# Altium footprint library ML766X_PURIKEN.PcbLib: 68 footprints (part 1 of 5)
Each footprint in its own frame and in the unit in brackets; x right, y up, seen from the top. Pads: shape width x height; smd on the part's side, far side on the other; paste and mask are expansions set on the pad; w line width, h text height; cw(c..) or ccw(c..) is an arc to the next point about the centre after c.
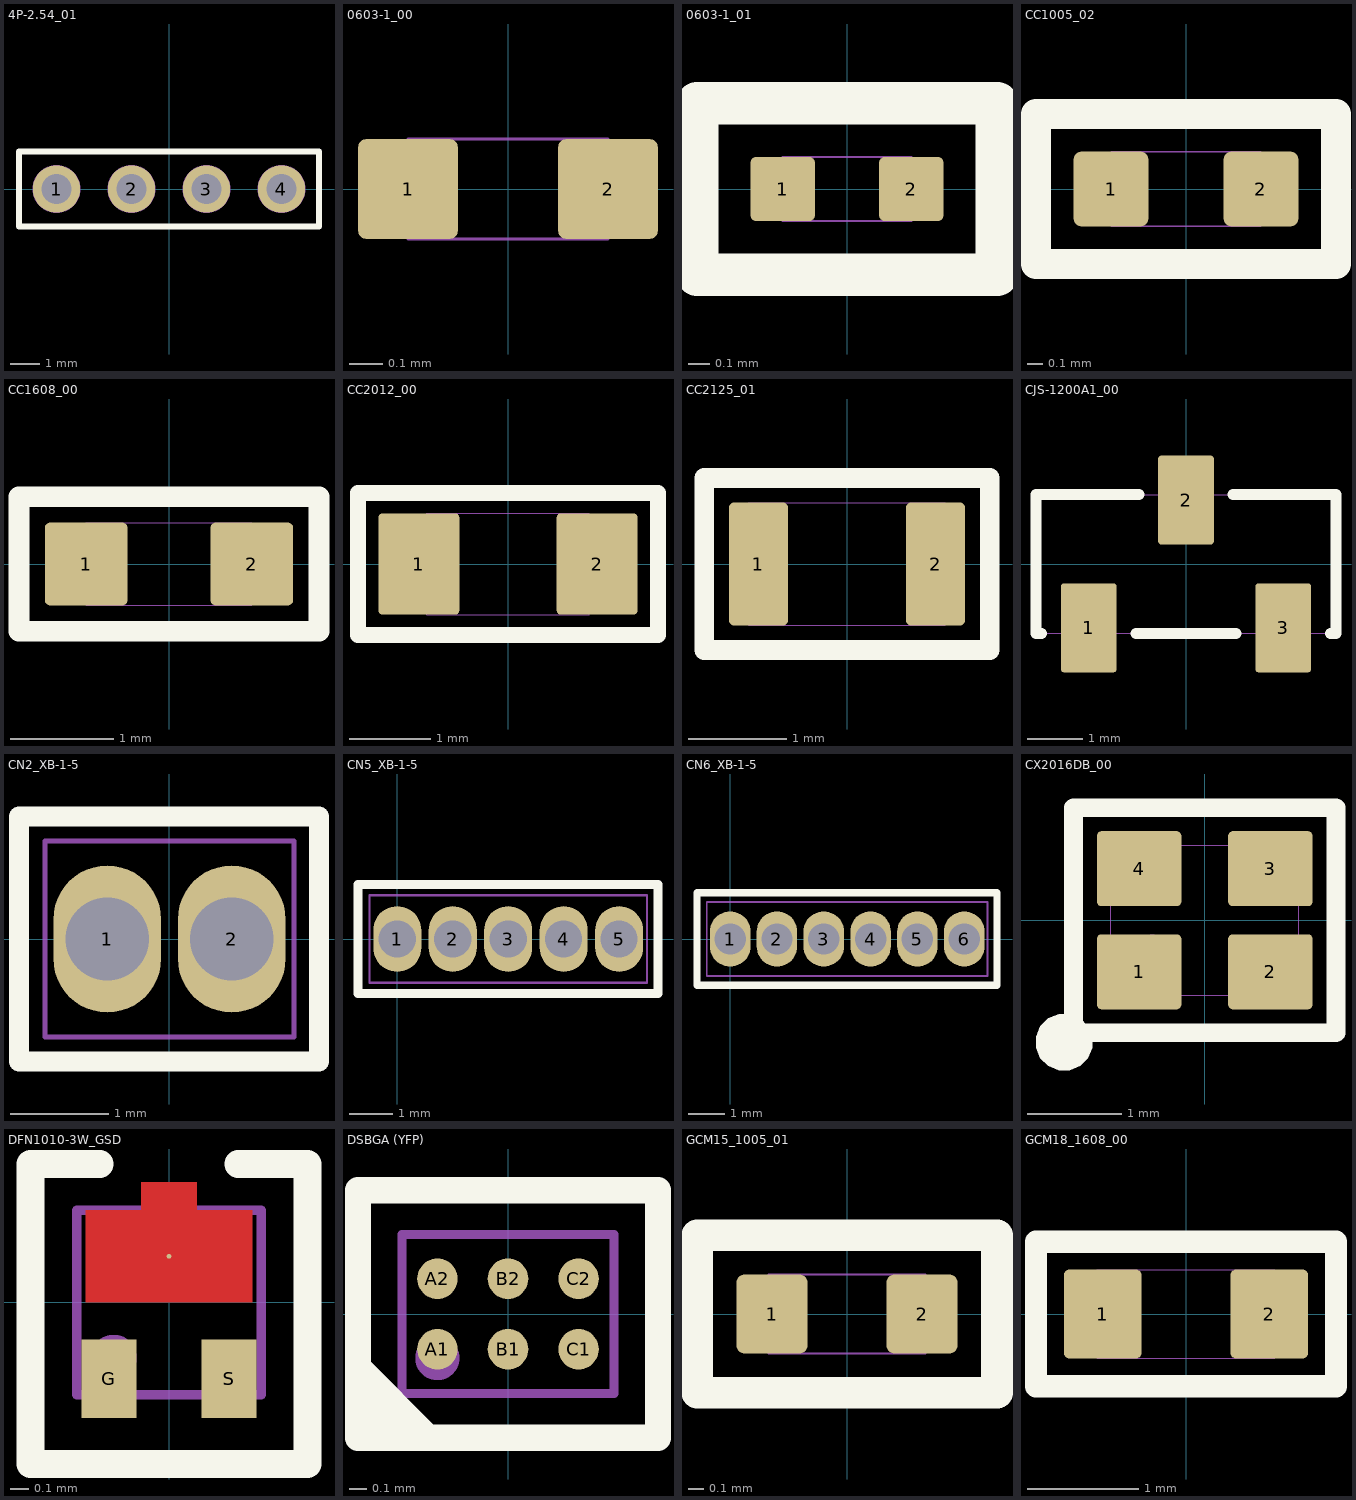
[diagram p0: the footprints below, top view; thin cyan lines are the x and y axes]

## 4P-2.54_01 [mm]
pads (4):
  round 1.6 / inner round 0 / far side round 1.6 hole 1: 1(-3.81,0) 2(-1.27,0) 3(1.27,0) 4(3.81,0)
Top Overlay:
  lines w0.2: -5.08,-1.27 -5.08,1.27 5.08,1.27 5.08,-1.27 -5.08,-1.27
Top Component Outline:
  lines w0.05: -5.08,-1.27 -5.08,1.27 5.08,1.27 5.08,-1.27 -5.08,-1.27
Mechanical 16:
  drawing of 4 lines, arcs and shapes, not listed

## 0603-1_00 [mm]
pads (2):
  rrect17% 0.3x0.3 smd: 1(-0.3,0) 2(0.3,0)
Top Component Outline:
  lines w0.01: -0.3,-0.15 -0.3,0.15 0.3,0.15 0.3,-0.15 -0.3,-0.15
3D body "CAPC0603X30N.step": height 0.32, standoff 0, extent -0.3,-0.16 0.3,0.16

## 0603-1_01 [mm]
pads (2):
  rrect17% 0.3x0.3 smd paste-2539.97: 1(-0.3,0) 2(0.3,0)
Top Overlay:
  lines w0.2: -0.7,-0.4 -0.7,0.4 0.7,0.4 0.7,-0.4 -0.7,-0.4
Top Component Outline:
  lines w0.01: -0.3,-0.15 -0.3,0.15 0.3,0.15 0.3,-0.15 -0.3,-0.15
3D body "RESC0603X25N.step": height 0.25, standoff 0, extent -0.3,-0.15 0.3,0.15

## CC1005_02 [mm]
pads (2):
  rrect22% 0.5x0.5 smd: 1(-0.5,0) 2(0.5,0)
Top Overlay:
  lines w0.2: -1,-0.5 1,-0.5 1,0.5 -1,0.5 -1,-0.5
Top Component Outline:
  lines w0.01: -0.5,-0.25 0.5,-0.25 0.5,0.25 -0.5,0.25 -0.5,-0.25
3D body "CAPC1005X50N.step": height 0.52, standoff 0, extent -0.5,-0.26 0.5,0.26

## CC1608_00 [mm]
height 0.5
pads (2):
  rrect12% 0.8x0.8 smd: 1(-0.8,0) 2(0.8,0)
Top Overlay:
  lines w0.2: -1.45,-0.65 -1.45,0.65 1.45,0.65 1.45,-0.65 0,-0.65 -1.45,-0.65
Top Component Outline:
  lines w0.01: -0.8,-0.4 -0.8,0.4 0.8,0.4 0.8,-0.4 -0.8,-0.4
3D body "CAPC1608X80N.step": height 0.82, standoff 0, extent -0.8,-0.41 0.8,0.41

## CC2012_00 [mm]
height 0.5
pads (2):
  rrect10% 1x1.25 smd: 1(-1.1,0) 2(1.1,0)
Top Overlay:
  lines w0.2: -1.85,-0.875 0,-0.875 1.85,-0.875 1.85,0.875 -1.85,0.875 -1.85,-0.875
Top Component Outline:
  lines w0.01: -1,-0.625 1,-0.625 1,0.625 -1,0.625 -1,-0.625
3D body "CAPC2012X85N.step": height 0.87, standoff 0, extent -1,-0.635 1,0.635

## CC2125_01 [mm]
height 0.85
pads (2):
  rrect17% 0.6x1.25 smd: 1(-0.9,0) 2(0.9,0)
Top Overlay:
  lines w0.2: -1.45,-0.875 -1.45,0.875 1.45,0.875 1.45,-0.875 0,-0.875 -1.45,-0.875
Top Component Outline:
  lines w0.01: -1,-0.625 -1,0.625 1,0.625 1,-0.625 -1,-0.625
3D body "CAPC2012X85N.step": height 0.87, standoff 0, extent -1,-0.635 1,0.635

## CJS-1200A1_00 [mm]
height 2.5
pads (3):
  rrect10% 1x1.6 smd: 1(-1.75,-1.15) 2(0,1.15) 3(1.75,-1.15)
Top Overlay:
  lines w0.2: -2.6,-1.25 -2.7,-1.25 -2.7,1.25 -0.85,1.25 ; -0.9,-1.25 0.9,-1.25 ; 0.85,1.25 2.7,1.25 2.7,-1.25 2.6,-1.25
Top Component Outline:
  lines w0.01: -2.7,-1.25 2.7,-1.25 2.7,1.25 -2.7,1.25 -2.7,-1.25
3D body: height 2.5, standoff 0, extent -2.7,-1.25 2.7,1.25

## CN2_XB-1-5 [mm] "XB-1-5-2P プリント板ニ段重ね用コンスルー"
height 5
pads (2):
  oval 1.1x1.5 hole 0.85 mask-2539.97: 1(-0.635,0) 2(0.635,0)
Top Overlay:
  lines w0.2: -1.535,-1.25 1.525,-1.25 1.525,1.25 -1.535,1.25 -1.535,-1.25
Top Solder:
  lines w1.16: -0.635,-0.22 -0.635,0.22 ; 0.635,-0.22 0.635,0.22
Bottom Solder:
  lines w1.16: -0.635,-0.22 -0.635,0.22 ; 0.635,-0.22 0.635,0.22
Top Component Outline:
  lines w0.05: -1.27,-1 1.27,-1 1.27,1 -1.27,1 -1.27,-1

## CN5_XB-1-5 [mm] "XB-1-5-5P プリント板ニ段重ね用コンスルー"
height 5
pads (5):
  oval 1.1x1.5 hole 0.85 mask-2539.97: 1(0,0) 2(1.27,0) 3(2.54,0) 4(3.81,0) 5(5.08,0)
Top Overlay:
  lines w0.2: -0.9,-1.25 -0.9,1.25 5.97,1.25 5.97,-1.25 -0.9,-1.25
Top Solder:
  lines w1.16: 0,-0.22 0,0.22 ; 1.27,-0.22 1.27,0.22 ; 2.54,-0.22 2.54,0.22 ; 3.81,-0.22 3.81,0.22 ; 5.08,-0.22 5.08,0.22
Bottom Solder:
  lines w1.16: 0,-0.22 0,0.22 ; 1.27,-0.22 1.27,0.22 ; 2.54,-0.22 2.54,0.22 ; 3.81,-0.22 3.81,0.22 ; 5.08,-0.22 5.08,0.22
Top Component Outline:
  lines w0.05: -0.635,-1 5.715,-1 5.715,1 -0.635,1 -0.635,-1

## CN6_XB-1-5 [mm] "XB-1-5-6P プリント板ニ段重ね用コンスルー"
height 5
pads (6):
  oval 1.1x1.5 hole 0.85 mask-2539.97: 1(0,0) 2(1.27,0) 3(2.54,0) 4(3.81,0) 5(5.08,0) 6(6.35,0)
Top Overlay:
  lines w0.2: 7.227,1.25 -0.9,1.25 -0.9,-1.25 7.24,-1.25 7.24,1.25
Top Solder:
  lines w1.16: 0,-0.22 0,0.22 ; 1.27,-0.22 1.27,0.22 ; 2.54,-0.22 2.54,0.22 ; 3.81,-0.22 3.81,0.22 ; 5.08,-0.22 5.08,0.22 ; 6.35,-0.22 6.35,0.22
Bottom Solder:
  lines w1.16: 0,-0.22 0,0.22 ; 1.27,-0.22 1.27,0.22 ; 2.54,-0.22 2.54,0.22 ; 3.81,-0.22 3.81,0.22 ; 5.08,-0.22 5.08,0.22 ; 6.35,-0.22 6.35,0.22
Top Component Outline:
  lines w0.05: -0.635,-1 -0.635,1 6.985,1 6.985,-1 -0.635,-1

## CX2016DB_00 [mm]
height 0.4
pads (4):
  rrect12% 0.9x0.8 smd: 1(-0.7,-0.55) 2(0.7,-0.55) 3(0.7,0.55) 4(-0.7,0.55)
Top Overlay:
  region: -1.2,-1.3 -1.2,-1.24 -1.246,-1.13 -1.33,-1.046 -1.44,-1 -1.56,-1 -1.67,-1.046 -1.754,-1.13 -1.8,-1.24 -1.8,-1.36 -1.754,-1.47 -1.67,-1.554 -1.56,-1.6 -1.5,-1.6 -1.44,-1.6 -1.33,-1.554 -1.246,-1.47 -1.2,-1.36 -1.2,-1.24 -1.246,-1.13 -1.33,-1.046 -1.44,-1 -1.56,-1 -1.67,-1.046 -1.754,-1.13 -1.8,-1.24 -1.8,-1.3 -1.8,-1.36 -1.754,-1.47 -1.67,-1.554 -1.56,-1.6 -1.44,-1.6 -1.33,-1.554 -1.246,-1.47 -1.2,-1.36 -1.2,-1.24 -1.246,-1.13 -1.33,-1.046 -1.44,-1 -1.5,-1 -1.56,-1 -1.67,-1.046 -1.754,-1.13 -1.8,-1.24 -1.8,-1.36 -1.754,-1.47 -1.67,-1.554 -1.56,-1.6 -1.44,-1.6 -1.33,-1.554 -1.246,-1.47 -1.2,-1.36
  lines w0.2: -1.4,-1.2 1.4,-1.2 1.4,1.2 -1.4,1.2 -1.4,-1.2
Top Component Outline:
  circle w0.01: c-0.55,-0.39 r0.23
  lines w0.01: -1,-0.8 1,-0.8 1,0.8 -1,0.8 -1,-0.8
3D body: height 0.4, standoff 0, extent -1,-0.8 1,0.8

## DFN1010-3W_GSD [mm]
height 0.45
pads (3):
  round 0.025 smd: D(0,0.25)
  rect 0.3x0.425 smd: G(-0.325,-0.412) S(0.325,-0.412)
Top Layer:
  region: -0.15,0.5 -0.15,0.65 0.15,0.65 0.15,0.5 0.45,0.5 0.45,0 -0.45,0 -0.45,0.5
Top Overlay:
  lines w0.15: -0.375,0.75 -0.75,0.75 -0.75,-0.875 0.75,-0.875 0.75,0.75 0.375,0.75
Top Component Outline:
  circle w0.2: c-0.3,-0.3 r0.025
  lines w0.01: -0.45,-0.5 -0.45,-0.25 -0.2,-0.25 -0.2,-0.5 ; 0.2,-0.5 0.2,-0.25 0.45,-0.25 0.45,-0.5
  lines w0.05: -0.5,-0.5 0.5,-0.5 0.5,0.5 -0.5,0.5 -0.5,-0.5
3D body "DFN1010-3W_Rev0.step": height 0.41, standoff 0.01, extent -0.48,-0.51 0.52,0.51

## DSBGA (YFP) [mm]
height 0.5
pads (6):
  round 0.23 smd mask+0.05: A1(-0.4,-0.2) A2(-0.4,0.2) B1(0,-0.2) B2(0,0.2) C1(0.4,-0.2) C2(0.4,0.2)
Top Overlay:
  region: -0.85,-0.7 -0.85,-0.2 -0.35,-0.7
  lines w0.15: -0.85,-0.7 -0.85,0.7 0.85,0.7 0.85,-0.7 -0.85,-0.7
Top Component Outline:
  circle w0.2: c-0.4,-0.25 r0.025
  lines w0.05: -0.6,-0.45 -0.6,0.45 0.6,0.45 0.6,-0.45 -0.6,-0.45
3D body: height 0.5, standoff 0, extent -0.6,-0.45 0.6,0.45

## GCM15_1005_01 [mm]
height 0.5
pads (2):
  rrect22% 0.45x0.5 smd: 1(-0.475,0) 2(0.475,0)
Top Overlay:
  lines w0.2: -0.95,-0.5 -0.95,0.5 0.95,0.5 0.95,-0.5 -0.95,-0.5
Top Component Outline:
  lines w0.01: -0.5,-0.25 0.5,-0.25 0.5,0.25 -0.5,0.25 -0.5,-0.25
3D body "CAPC1005X50N.step": height 0.52, standoff 0, extent -0.5,-0.26 0.5,0.26

## GCM18_1608_00 [mm]
height 0.8
pads (2):
  rrect14% 0.7x0.8 smd: 1(-0.75,0) 2(0.75,0)
Top Overlay:
  lines w0.2: -1.35,-0.65 -1.35,0.65 1.35,0.65 1.35,-0.65 0,-0.65 -1.35,-0.65
Top Component Outline:
  lines w0.01: -0.8,-0.4 0.8,-0.4 0.8,0.4 -0.8,0.4 -0.8,-0.4
3D body "CAPC1608X80N.step": height 0.82, standoff 0, extent -0.8,-0.41 0.8,0.41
